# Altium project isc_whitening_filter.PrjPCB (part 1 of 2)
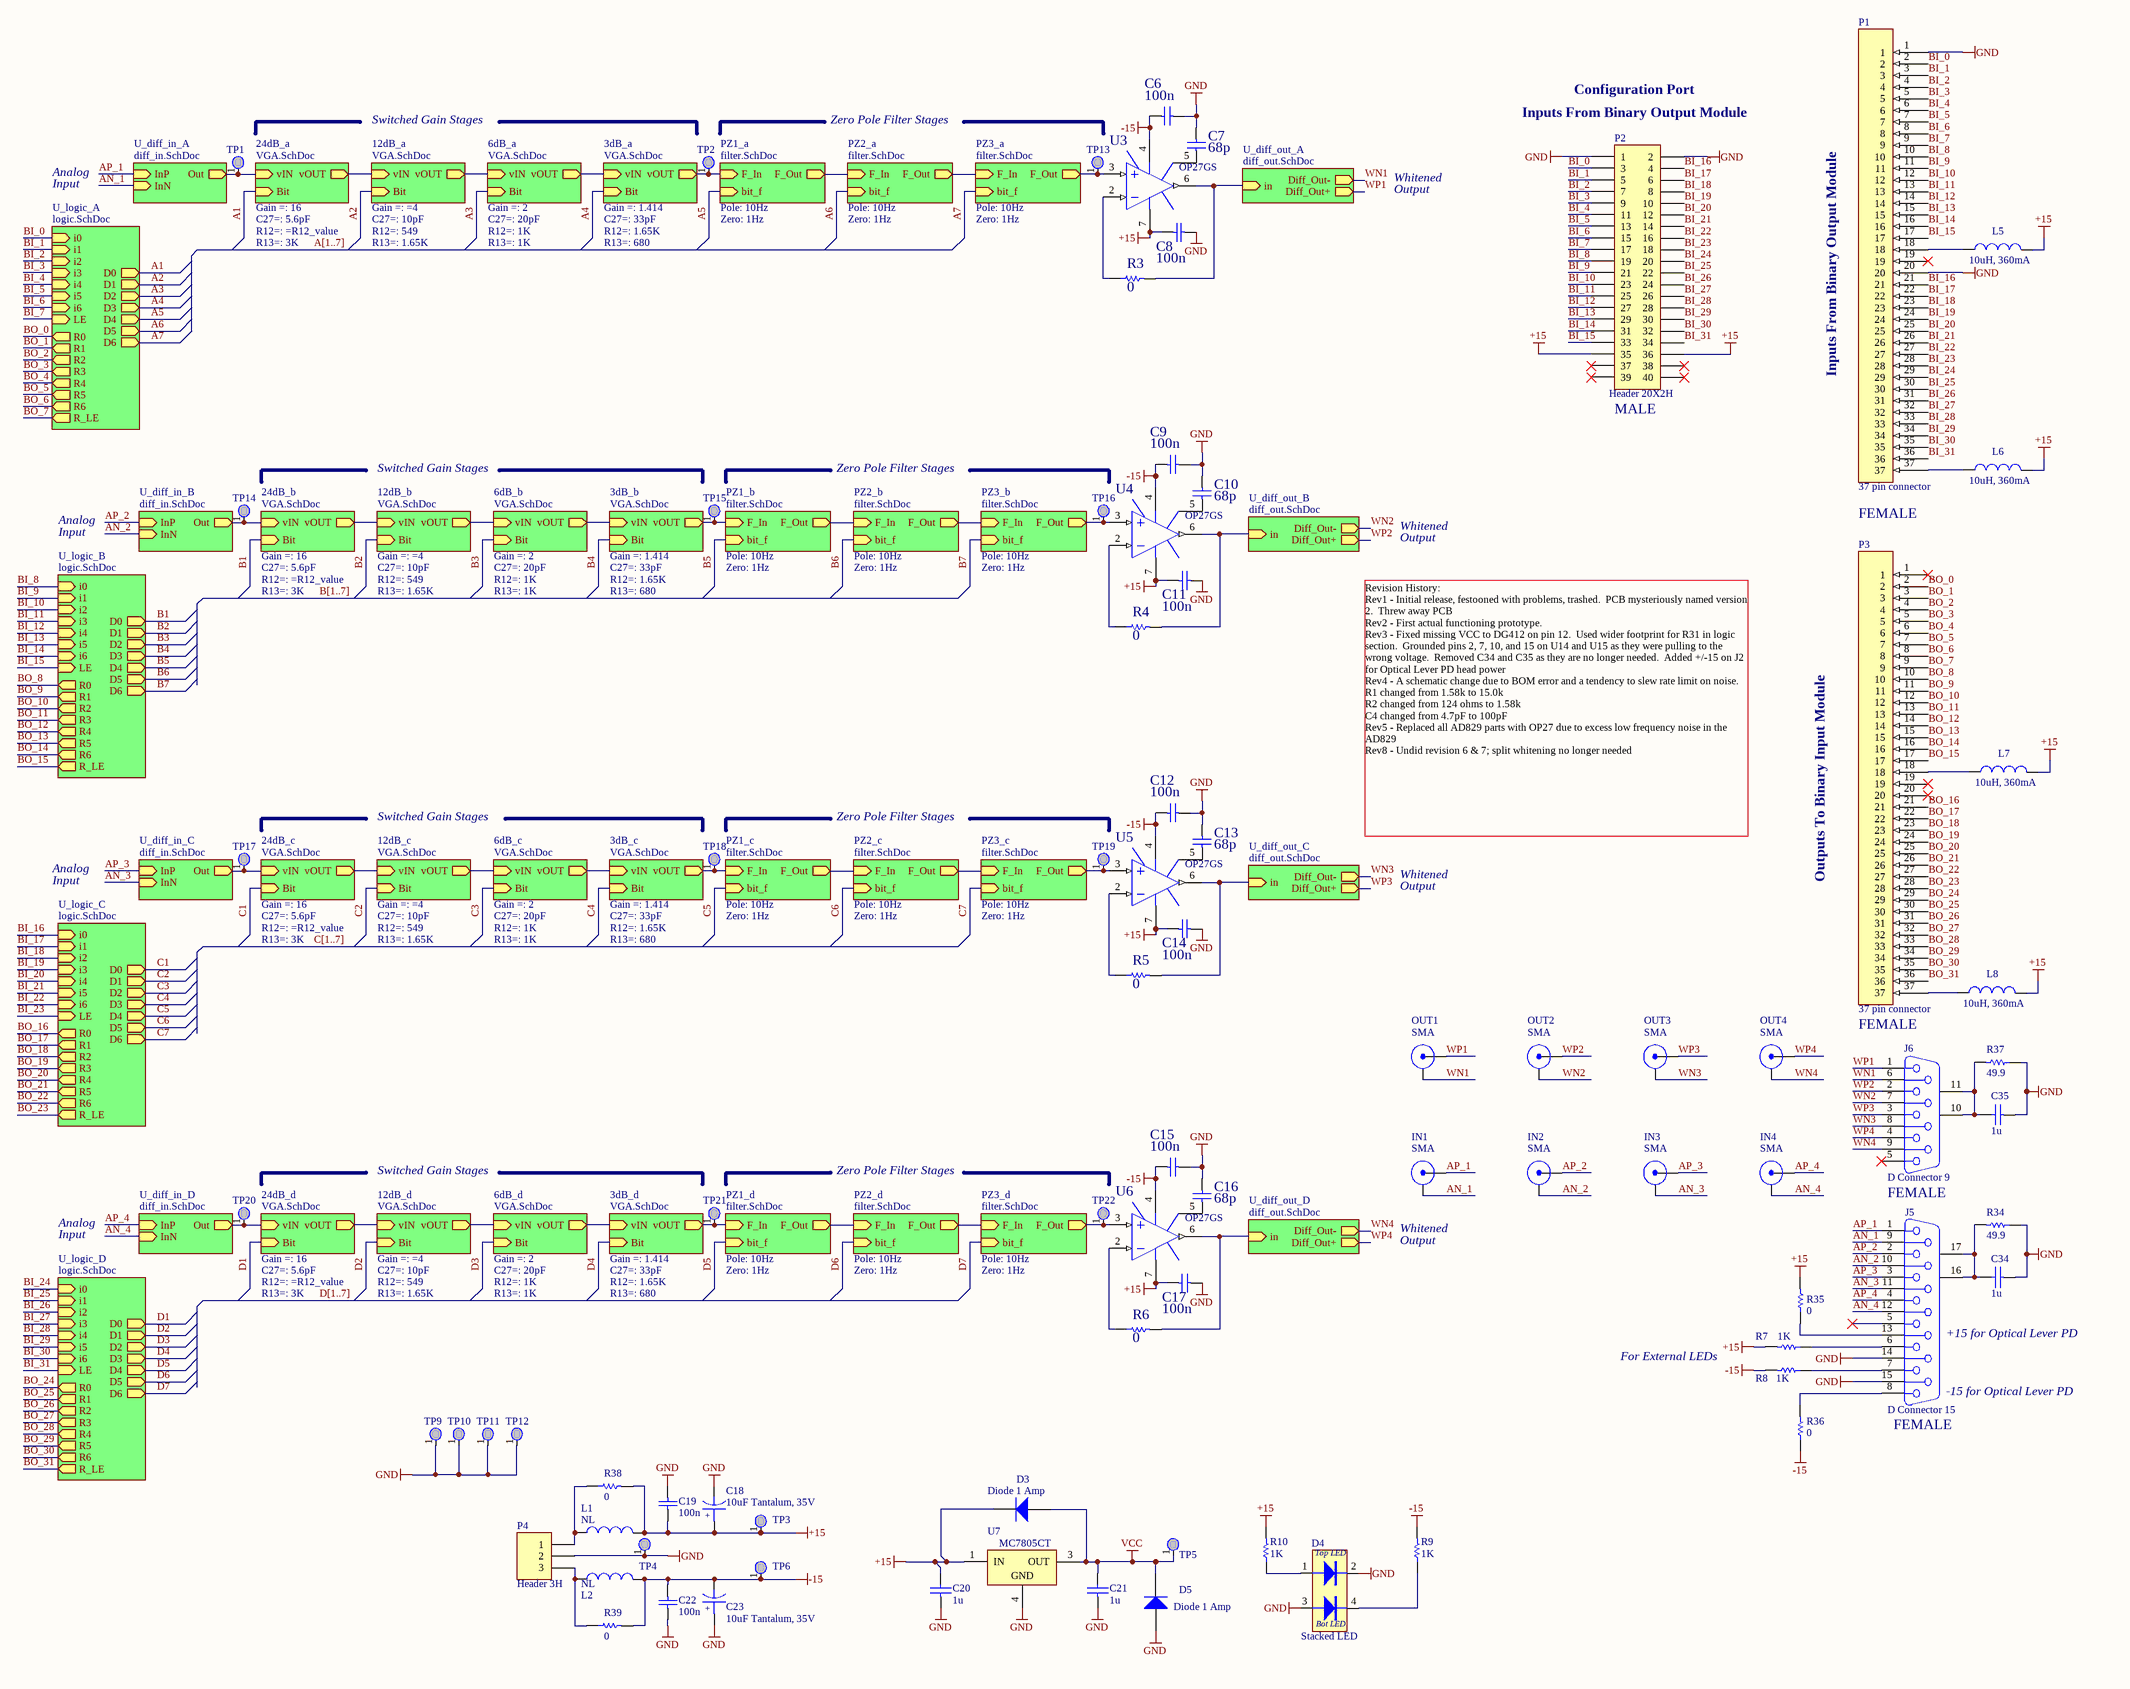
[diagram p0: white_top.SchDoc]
DCC: D1001530; REV: 8
6 sheets, 550 parts. Net scope: hierarchical (ports join the sheet entries above them; power ports are global).
Board file: isc_whitening_filter.PcbDoc
Sheets:
  white_top.SchDoc
    24dB_a = VGA.SchDoc
    12dB_a = VGA.SchDoc
    6dB_a = VGA.SchDoc
    3dB_a = VGA.SchDoc
    U_diff_in_A = diff_in.SchDoc
    U_diff_out_A = diff_out.SchDoc
    U_logic_A = logic.SchDoc
    U_diff_in_B = diff_in.SchDoc
    U_diff_out_B = diff_out.SchDoc
    U_logic_B = logic.SchDoc
    U_diff_in_C = diff_in.SchDoc
    U_diff_out_C = diff_out.SchDoc
    U_logic_C = logic.SchDoc
    U_diff_in_D = diff_in.SchDoc
    U_diff_out_D = diff_out.SchDoc
    U_logic_D = logic.SchDoc
    24dB_b = VGA.SchDoc
    12dB_b = VGA.SchDoc
    12dB_c = VGA.SchDoc
    12dB_d = VGA.SchDoc
    24dB_c = VGA.SchDoc
    24dB_d = VGA.SchDoc
    6dB_b = VGA.SchDoc
    6dB_c = VGA.SchDoc
    6dB_d = VGA.SchDoc
    3dB_b = VGA.SchDoc
    3dB_c = VGA.SchDoc
    3dB_d = VGA.SchDoc
    PZ1_b = filter.SchDoc
    PZ2_b = filter.SchDoc
    PZ3_b = filter.SchDoc
    PZ1_a = filter.SchDoc
    PZ2_a = filter.SchDoc
    PZ3_a = filter.SchDoc
    PZ1_c = filter.SchDoc
    PZ2_c = filter.SchDoc
    PZ3_c = filter.SchDoc
    PZ1_d = filter.SchDoc
    PZ2_d = filter.SchDoc
    PZ3_d = filter.SchDoc

## Sheet white_top.SchDoc: aLIGO ISC Whitening Filter
size C; SchematicNumber: DYYYYYYY-VX; PcbNumber: DXXXXXXX-VX; LastEdit: 06 Oct 2010; PageSetup: Record=PageOptions¦CenterHorizontal=True¦CenterVertical=True¦PrintScale=0.70¦XCorrection=1.00¦YCorrection=1.00¦PrintKind=0¦BorderSize=5000000¦LeftOffset=0¦BottomOffset=0¦Orientation=2¦PaperLength=4318¦PaperWidth=2794¦Scale=100¦PaperSource=7¦PrintQuality=600¦MediaType=1¦DitherType=10¦PaperKind=11x17¦PrintScaleMode=1; Organization: LIGO Laboratory; Address1: California Institute of Technology; Address2: Massachusetts Institute of Technology; DocumentNumber: D1001530; Revision: 8; SheetNumber: 1; SheetTotal: 6; Engineer: R.  Abbott

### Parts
C6  100n  [3216[1206]]
C7  68p  [3216[1206]]
C8  100n  [3216[1206]]
C9  100n  [3216[1206]]
C10  68p  [3216[1206]]
C11  100n  [3216[1206]]
C12  100n  [3216[1206]]
C13  68p  [3216[1206]]
C14  100n  [3216[1206]]
C15  100n  [3216[1206]]
C16  68p  [3216[1206]]
C17  100n  [3216[1206]]
C18  10uF Tantalum, 35V  [7343-31]
C19  100n  [3216[1206]]
C20  1u  [3216[1206]]
C21  1u  [3216[1206]]
C22  100n  [3216[1206]]
C23  10uF Tantalum, 35V  [7343-31]
C34  1u  [3216[1206]]
C35  1u  [3216[1206]]
D3  value Diode 1 Amp  [sod123]  (hidden comment: 60V, 1A Schottky)
D4  Stacked LED  [my LUMEX Dual LED]
D5  value Diode 1 Amp  [sod123]  (hidden comment: 60V, 1A Schottky)
IN1  SMA  [SMA]
IN2  SMA  [SMA]
IN3  SMA  [SMA]
IN4  SMA  [SMA]
J5  D Connector 15  [DSUB1.385-2H15]
J6  D Connector 9  [DSUB1.385-2H9]
L1  NL  [1812]
L2  NL  [1812]
L5  10uH, 360mA  [1812]
L6  10uH, 360mA  [1812]
L7  10uH, 360mA  [1812]
L8  10uH, 360mA  [1812]
OUT1  SMA  [SMA]
OUT2  SMA  [SMA]
OUT3  SMA  [SMA]
OUT4  SMA  [SMA]
P1  37 pin connector  [DB37/F/RA/125MT]
P2  Header 20X2H  [MY_40-pin_Header_RA]
P3  37 pin connector  [DB37/F/RA/125MT]
P4  Header 3H  [Molex_156_RA_3]
R3  0  [3216[1206]]
R4  0  [3216[1206]]
R5  0  [3216[1206]]
R6  0  [3216[1206]]
R7  1K  [3216[1206]]
R8  1K  [3216[1206]]
R9  1K  [3216[1206]]
R10  1K  [3216[1206]]
R34  49.9  [3216[1206]]
R35  0  [3216[1206]]
R36  0  [3216[1206]]
R37  49.9  [3216[1206]]
R38  0  [3216[1206]]
R39  0  [3216[1206]]
TP1  TEST POINT  [TP_SMT_MICRO]  (value not drawn)
TP2  TEST POINT  [TP_SMT_MICRO]  (value not drawn)
TP3  TEST POINT  [TP_SMT_MICRO]  (value not drawn)
TP4  TEST POINT  [TP_SMT_MICRO]  (value not drawn)
TP5  TEST POINT  [TP_SMT_MICRO]  (value not drawn)
TP6  TEST POINT  [TP_SMT_MICRO]  (value not drawn)
TP9  TEST POINT  [TP_SMT_MICRO]  (value not drawn)
TP10  TEST POINT  [TP_SMT_MICRO]  (value not drawn)
TP11  TEST POINT  [TP_SMT_MICRO]  (value not drawn)
TP12  TEST POINT  [TP_SMT_MICRO]  (value not drawn)
TP13  TEST POINT  [TP_SMT_MICRO]  (value not drawn)
TP14  TEST POINT  [TP_SMT_MICRO]  (value not drawn)
TP15  TEST POINT  [TP_SMT_MICRO]  (value not drawn)
TP16  TEST POINT  [TP_SMT_MICRO]  (value not drawn)
TP17  TEST POINT  [TP_SMT_MICRO]  (value not drawn)
TP18  TEST POINT  [TP_SMT_MICRO]  (value not drawn)
TP19  TEST POINT  [TP_SMT_MICRO]  (value not drawn)
TP20  TEST POINT  [TP_SMT_MICRO]  (value not drawn)
TP21  TEST POINT  [TP_SMT_MICRO]  (value not drawn)
TP22  TEST POINT  [TP_SMT_MICRO]  (value not drawn)
U3  OP27GS  [SOIC127P600-8N]
U4  OP27GS  [SOIC127P600-8N]
U5  OP27GS  [SOIC127P600-8N]
U6  OP27GS  [SOIC127P600-8N]
U7  MC7805CT  [MY_TO220]

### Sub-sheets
3dB_a = VGA.SchDoc: Bit (in), vIN (in), vOUT (out)  | R12_value: 1.65K; R13_value: 680; C27_value: 33pF; Gain =: 1.414; C27=: 33pF; R12=: 1.65K; R13=: 680
3dB_b = VGA.SchDoc: Bit (in), vIN (in), vOUT (out)  | R12_value: 1.65K; R13_value: 680; C27_value: 33pF; Gain =: 1.414; C27=: 33pF; R12=: 1.65K; R13=: 680
3dB_c = VGA.SchDoc: Bit (in), vIN (in), vOUT (out)  | R12_value: 1.65K; R13_value: 680; C27_value: 33pF; Gain =: 1.414; C27=: 33pF; R12=: 1.65K; R13=: 680
3dB_d = VGA.SchDoc: Bit (in), vIN (in), vOUT (out)  | R12_value: 1.65K; R13_value: 680; C27_value: 33pF; Gain =: 1.414; C27=: 33pF; R12=: 1.65K; R13=: 680
6dB_a = VGA.SchDoc: Bit (in), vIN (in), vOUT (out)  | C27_value: 20pF; Gain =: 2; R12_Value: 1K; R13_value: 1K; R12=: 1K; R13=: 1K; C27=: 20pF
6dB_b = VGA.SchDoc: Bit (in), vIN (in), vOUT (out)  | C27_value: 20pF; Gain =: 2; R12_Value: 1K; R13_value: 1K; R12=: 1K; R13=: 1K; C27=: 20pF
6dB_c = VGA.SchDoc: Bit (in), vIN (in), vOUT (out)  | C27_value: 20pF; Gain =: 2; R12_Value: 1K; R13_value: 1K; R12=: 1K; R13=: 1K; C27=: 20pF
6dB_d = VGA.SchDoc: Bit (in), vIN (in), vOUT (out)  | C27_value: 20pF; Gain =: 2; R12_Value: 1K; R13_value: 1K; R12=: 1K; R13=: 1K; C27=: 20pF
12dB_a = VGA.SchDoc: Bit (in), vIN (in), vOUT (out)  | C27_value: 10pF; Gain =: =4; R12=: 549; R12_value: 549; R13=: 1.65K; R13_value: 1.65K; C27=: 10pF
12dB_b = VGA.SchDoc: Bit (in), vIN (in), vOUT (out)  | C27_value: 10pF; Gain =: =4; R12=: 549; R12_value: 549; R13=: 1.65K; R13_value: 1.65K; C27=: 10pF
12dB_c = VGA.SchDoc: Bit (in), vIN (in), vOUT (out)  | C27_value: 10pF; Gain =: =4; R12=: 549; R12_value: 549; R13=: 1.65K; R13_value: 1.65K; C27=: 10pF
12dB_d = VGA.SchDoc: Bit (in), vIN (in), vOUT (out)  | C27_value: 10pF; Gain =: =4; R12=: 549; R12_value: 549; R13=: 1.65K; R13_value: 1.65K; C27=: 10pF
24dB_a = VGA.SchDoc: Bit (in), vIN (in), vOUT (out)  | C27=: 5.6pF; C27_value: 5.6pF; R12=: =R12_value; R13=: 3K; R13_value: 3K; R12_value: 200; Gain =: 16
24dB_b = VGA.SchDoc: Bit (in), vIN (in), vOUT (out)  | C27=: 5.6pF; C27_value: 5.6pF; R12=: =R12_value; R13=: 3K; R13_value: 3K; R12_value: 200; Gain =: 16
24dB_c = VGA.SchDoc: Bit (in), vIN (in), vOUT (out)  | C27=: 5.6pF; C27_value: 5.6pF; R12=: =R12_value; R13=: 3K; R13_value: 3K; R12_value: 200; Gain =: 16
24dB_d = VGA.SchDoc: Bit (in), vIN (in), vOUT (out)  | C27=: 5.6pF; C27_value: 5.6pF; R12=: =R12_value; R13=: 3K; R13_value: 3K; R12_value: 200; Gain =: 16
PZ1_a = filter.SchDoc: bit_f (in), F_Out (out), F_In (in)  | Pole: 10Hz; Zero: 1Hz; C5_value: 10e-6
PZ1_b = filter.SchDoc: bit_f (in), F_Out (out), F_In (in)  | Pole: 10Hz; Zero: 1Hz; C5_value: 10e-6
PZ1_c = filter.SchDoc: bit_f (in), F_Out (out), F_In (in)  | Pole: 10Hz; Zero: 1Hz; C5_value: 10e-6
PZ1_d = filter.SchDoc: bit_f (in), F_Out (out), F_In (in)  | Pole: 10Hz; Zero: 1Hz; C5_value: 10e-6
PZ2_a = filter.SchDoc: bit_f (in), F_Out (out), F_In (in)  | Pole: 10Hz; Zero: 1Hz; C5_value: 10e-6
PZ2_b = filter.SchDoc: bit_f (in), F_Out (out), F_In (in)  | Pole: 10Hz; Zero: 1Hz; C5_value: 10e-6
PZ2_c = filter.SchDoc: bit_f (in), F_Out (out), F_In (in)  | Pole: 10Hz; Zero: 1Hz; C5_value: 10e-6
PZ2_d = filter.SchDoc: bit_f (in), F_Out (out), F_In (in)  | Pole: 10Hz; Zero: 1Hz; C5_value: 10e-6
PZ3_a = filter.SchDoc: bit_f (in), F_Out (out), F_In (in)  | Pole: 10Hz; Zero: 1Hz; C5_value: 10e-6
PZ3_b = filter.SchDoc: bit_f (in), F_Out (out), F_In (in)  | Pole: 10Hz; Zero: 1Hz; C5_value: 10e-6
PZ3_c = filter.SchDoc: bit_f (in), F_Out (out), F_In (in)  | Pole: 10Hz; Zero: 1Hz; C5_value: 10e-6
PZ3_d = filter.SchDoc: bit_f (in), F_Out (out), F_In (in)  | Pole: 10Hz; Zero: 1Hz; C5_value: 10e-6
U_diff_in_A = diff_in.SchDoc: InP (in), InN (in), Out (out)
U_diff_in_B = diff_in.SchDoc: InP (in), InN (in), Out (out)
U_diff_in_C = diff_in.SchDoc: InP (in), InN (in), Out (out)
U_diff_in_D = diff_in.SchDoc: InP (in), InN (in), Out (out)
U_diff_out_A = diff_out.SchDoc: Diff_Out- (out), Diff_Out+ (out), in (in)
U_diff_out_B = diff_out.SchDoc: Diff_Out- (out), Diff_Out+ (out), in (in)
U_diff_out_C = diff_out.SchDoc: Diff_Out- (out), Diff_Out+ (out), in (in)
U_diff_out_D = diff_out.SchDoc: Diff_Out- (out), Diff_Out+ (out), in (in)
U_logic_A = logic.SchDoc: D0 (out), D1 (out), D2 (out), D3 (out), D4 (out), D5 (out), D6 (out), R0 (out), R1 (out), R2 (out), R3 (out), R4 (out), R5 (out), R6 (out), R_LE (out), i0 (in), i1 (in), i2 (in), i3 (in), i4 (in), i5 (in), i6 (in), LE (in)
U_logic_B = logic.SchDoc: D0 (out), D1 (out), D2 (out), D3 (out), D4 (out), D5 (out), D6 (out), R0 (out), R1 (out), R2 (out), R3 (out), R4 (out), R5 (out), R6 (out), R_LE (out), i0 (in), i1 (in), i2 (in), i3 (in), i4 (in), i5 (in), i6 (in), LE (in)
U_logic_C = logic.SchDoc: D0 (out), D1 (out), D2 (out), D3 (out), D4 (out), D5 (out), D6 (out), R0 (out), R1 (out), R2 (out), R3 (out), R4 (out), R5 (out), R6 (out), R_LE (out), i0 (in), i1 (in), i2 (in), i3 (in), i4 (in), i5 (in), i6 (in), LE (in)
U_logic_D = logic.SchDoc: D0 (out), D1 (out), D2 (out), D3 (out), D4 (out), D5 (out), D6 (out), R0 (out), R1 (out), R2 (out), R3 (out), R4 (out), R5 (out), R6 (out), R_LE (out), i0 (in), i1 (in), i2 (in), i3 (in), i4 (in), i5 (in), i6 (in), LE (in)

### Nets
+15: C8.2 C11.2 C14.2 C17.2 C18.1 C19.1 C20.2 D3.2(K) L1.2 L5.2 L6.2 L7.2 L8.2 P2.35 P2.36 R7.2 R10.2 R35.2 R38.2 TP3.1 U3.7(V+) U4.7(V+) U5.7(V+) U6.7(V+) U7.1(IN)
-15: C6.2 C9.2 C12.2 C15.2 C22.1 C23.2 L2.2 R8.2 R9.2 R36.1 R39.2 TP6.1 U3.4(V-) U4.4(V-) U5.4(V-) U6.4(V-)
GND: C6.1 C7.1 C8.1 C9.1 C10.1 C11.1 C12.1 C13.1 C14.1 C15.1 C16.1 C17.1 C18.2 C19.2 C20.1 C21.1 C22.2 C23.1 C34.1 C35.1 D4.2(CATHODE) D4.3(ANODE) D5.1(A) J5.14 J5.15 P1.1 P1.20 P2.1 P2.2 P4.2 R34.1 R37.1 TP4.1 TP9.1 TP10.1 TP11.1 TP12.1 U7.4(GND)
VCC: C21.2 D3.1(A) D5.2(K) TP5.1 U7.3(OUT)
A1: sheet 24dB_a/Bit, sheet U_logic_A/D0
A2: sheet 12dB_a/Bit, sheet U_logic_A/D1
A3: sheet 6dB_a/Bit, sheet U_logic_A/D2
A4: sheet 3dB_a/Bit, sheet U_logic_A/D3
A5: sheet U_logic_A/D4, sheet PZ1_a/bit_f
A6: sheet U_logic_A/D5, sheet PZ2_a/bit_f
A7: sheet U_logic_A/D6, sheet PZ3_a/bit_f
AN_1: IN1.2(Y) J5.9 ; sheet U_diff_in_A/InN
AN_2: IN2.2(Y) J5.10 ; sheet U_diff_in_B/InN
AN_3: IN3.2(Y) J5.11 ; sheet U_diff_in_C/InN
AN_4: IN4.2(Y) J5.12 ; sheet U_diff_in_D/InN
AP_1: IN1.1(X) J5.1 ; sheet U_diff_in_A/InP
AP_2: IN2.1(X) J5.2 ; sheet U_diff_in_B/InP
AP_3: IN3.1(X) J5.3 ; sheet U_diff_in_C/InP
AP_4: IN4.1(X) J5.4 ; sheet U_diff_in_D/InP
B1: sheet U_logic_B/D0, sheet 24dB_b/Bit
B2: sheet U_logic_B/D1, sheet 12dB_b/Bit
B3: sheet U_logic_B/D2, sheet 6dB_b/Bit
B4: sheet U_logic_B/D3, sheet 3dB_b/Bit
B5: sheet U_logic_B/D4, sheet PZ1_b/bit_f
B6: sheet U_logic_B/D5, sheet PZ2_b/bit_f
B7: sheet U_logic_B/D6, sheet PZ3_b/bit_f
BI_0: P1.2 P2.3 ; sheet U_logic_A/i0
BI_1: P1.3 P2.5 ; sheet U_logic_A/i1
BI_2: P1.4 P2.7 ; sheet U_logic_A/i2
BI_3: P1.5 P2.9 ; sheet U_logic_A/i3
BI_4: P1.6 P2.11 ; sheet U_logic_A/i4
BI_5: P1.7 P2.13 ; sheet U_logic_A/i5
BI_6: P1.8 P2.15 ; sheet U_logic_A/i6
BI_7: P1.9 P2.17 ; sheet U_logic_A/LE
BI_8: P1.10 P2.19 ; sheet U_logic_B/i0
BI_9: P1.11 P2.21 ; sheet U_logic_B/i1
BI_10: P1.12 P2.23 ; sheet U_logic_B/i2
BI_11: P1.13 P2.25 ; sheet U_logic_B/i3
BI_12: P1.14 P2.27 ; sheet U_logic_B/i4
BI_13: P1.15 P2.29 ; sheet U_logic_B/i5
BI_14: P1.16 P2.31 ; sheet U_logic_B/i6
BI_15: P1.17 P2.33 ; sheet U_logic_B/LE
BI_16: P1.21 P2.4 ; sheet U_logic_C/i0
BI_17: P1.22 P2.6 ; sheet U_logic_C/i1
BI_18: P1.23 P2.8 ; sheet U_logic_C/i2
BI_19: P1.24 P2.10 ; sheet U_logic_C/i3
BI_20: P1.25 P2.12 ; sheet U_logic_C/i4
BI_21: P1.26 P2.14 ; sheet U_logic_C/i5
BI_22: P1.27 P2.16 ; sheet U_logic_C/i6
BI_23: P1.28 P2.18 ; sheet U_logic_C/LE
BI_24: P1.29 P2.20 ; sheet U_logic_D/i0
BI_25: P1.30 P2.22 ; sheet U_logic_D/i1
BI_26: P1.31 P2.24 ; sheet U_logic_D/i2
BI_27: P1.32 P2.26 ; sheet U_logic_D/i3
BI_28: P1.33 P2.28 ; sheet U_logic_D/i4
BI_29: P1.34 P2.30 ; sheet U_logic_D/i5
BI_30: P1.35 P2.32 ; sheet U_logic_D/i6
BI_31: P1.36 P2.34 ; sheet U_logic_D/LE
BO_0: P3.2 ; sheet U_logic_A/R0
BO_1: P3.3 ; sheet U_logic_A/R1
BO_2: P3.4 ; sheet U_logic_A/R2
BO_3: P3.5 ; sheet U_logic_A/R3
BO_4: P3.6 ; sheet U_logic_A/R4
BO_5: P3.7 ; sheet U_logic_A/R5
BO_6: P3.8 ; sheet U_logic_A/R6
BO_7: P3.9 ; sheet U_logic_A/R_LE
BO_8: P3.10 ; sheet U_logic_B/R0
BO_9: P3.11 ; sheet U_logic_B/R1
BO_10: P3.12 ; sheet U_logic_B/R2
BO_11: P3.13 ; sheet U_logic_B/R3
BO_12: P3.14 ; sheet U_logic_B/R4
BO_13: P3.15 ; sheet U_logic_B/R5
BO_14: P3.16 ; sheet U_logic_B/R6
BO_15: P3.17 ; sheet U_logic_B/R_LE
BO_16: P3.21 ; sheet U_logic_C/R0
BO_17: P3.22 ; sheet U_logic_C/R1
BO_18: P3.23 ; sheet U_logic_C/R2
BO_19: P3.24 ; sheet U_logic_C/R3
BO_20: P3.25 ; sheet U_logic_C/R4
BO_21: P3.26 ; sheet U_logic_C/R5
BO_22: P3.27 ; sheet U_logic_C/R6
BO_23: P3.28 ; sheet U_logic_C/R_LE
BO_24: P3.29 ; sheet U_logic_D/R0
BO_25: P3.30 ; sheet U_logic_D/R1
BO_26: P3.31 ; sheet U_logic_D/R2
BO_27: P3.32 ; sheet U_logic_D/R3
BO_28: P3.33 ; sheet U_logic_D/R4
BO_29: P3.34 ; sheet U_logic_D/R5
BO_30: P3.35 ; sheet U_logic_D/R6
BO_31: P3.36 ; sheet U_logic_D/R_LE
C1: sheet U_logic_C/D0, sheet 24dB_c/Bit
C2: sheet U_logic_C/D1, sheet 12dB_c/Bit
C3: sheet U_logic_C/D2, sheet 6dB_c/Bit
C4: sheet U_logic_C/D3, sheet 3dB_c/Bit
C5: sheet U_logic_C/D4, sheet PZ1_c/bit_f
C6: sheet U_logic_C/D5, sheet PZ2_c/bit_f
C7: sheet U_logic_C/D6, sheet PZ3_c/bit_f
D1: sheet U_logic_D/D0, sheet 24dB_d/Bit
D2: sheet U_logic_D/D1, sheet 12dB_d/Bit
D3: sheet U_logic_D/D2, sheet 6dB_d/Bit
D4: sheet U_logic_D/D3, sheet 3dB_d/Bit
D5: sheet U_logic_D/D4, sheet PZ1_d/bit_f
D6: sheet U_logic_D/D5, sheet PZ2_d/bit_f
D7: sheet U_logic_D/D6, sheet PZ3_d/bit_f
WN1: J6.6 OUT1.2(Y) ; sheet U_diff_out_A/Diff_Out-
WN2: J6.7 OUT2.2(Y) ; sheet U_diff_out_B/Diff_Out-
WN3: J6.8 OUT3.2(Y) ; sheet U_diff_out_C/Diff_Out-
WN4: J6.9 OUT4.2(Y) ; sheet U_diff_out_D/Diff_Out-
WP1: J6.1 OUT1.1(X) ; sheet U_diff_out_A/Diff_Out+
WP2: J6.2 OUT2.1(X) ; sheet U_diff_out_B/Diff_Out+
WP3: J6.3 OUT3.1(X) ; sheet U_diff_out_C/Diff_Out+
WP4: J6.4 OUT4.1(X) ; sheet U_diff_out_D/Diff_Out+
NetC7_2: C7.2 U3.5(NUL)
NetC10_2: C10.2 U4.5(NUL)
NetC13_2: C13.2 U5.5(NUL)
NetC16_2: C16.2 U6.5(NUL)
NetC34_2: C34.2 J5.16(MH1) J5.17(MH2) R34.2
NetC35_2: C35.2 J6.10(MH1) J6.11(MH2) R37.2
NetC39_U_diff_in_A_2: TP1.1 ; sheet 24dB_a/vIN, sheet U_diff_in_A/Out
NetC39_U_diff_in_B_2: TP14.1 ; sheet U_diff_in_B/Out, sheet 24dB_b/vIN
NetC39_U_diff_in_C_2: TP17.1 ; sheet U_diff_in_C/Out, sheet 24dB_c/vIN
NetC39_U_diff_in_D_2: TP20.1 ; sheet U_diff_in_D/Out, sheet 24dB_d/vIN
NetD4_1: D4.1(COM) R10.1
NetD4_4: D4.4(ANODE) R9.1
NetJ5_6: J5.6 R7.1
NetJ5_7: J5.7 R8.1
NetJ5_8: J5.8 R36.2
NetJ5_13: J5.13 R35.1
NetL1_1: L1.1 P4.1 R38.1
NetL2_1: L2.1 P4.3 R39.1
NetL5_1: L5.1 P1.18
NetL6_1: L6.1 P1.37
NetL7_1: L7.1 P3.18
NetL8_1: L8.1 P3.37
NetR3_1: R3.1 U3.2(IN-)
NetR3_2: R3.2 U3.6(OUT) ; sheet U_diff_out_A/in
NetR4_1: R4.1 U4.2(IN-)
NetR4_2: R4.2 U4.6(OUT) ; sheet U_diff_out_B/in
NetR5_1: R5.1 U5.2(IN-)
NetR5_2: R5.2 U5.6(OUT) ; sheet U_diff_out_C/in
NetR6_1: R6.1 U6.2(IN-)
NetR6_2: R6.2 U6.6(OUT) ; sheet U_diff_out_D/in
NetTP2_1: TP2.1 ; sheet 3dB_a/vOUT, sheet PZ1_a/F_In
NetTP13_1: TP13.1 U3.3(IN+) ; sheet PZ3_a/F_Out
NetTP15_1: TP15.1 ; sheet 3dB_b/vOUT, sheet PZ1_b/F_In
NetTP16_1: TP16.1 U4.3(IN+) ; sheet PZ3_b/F_Out
NetTP18_1: TP18.1 ; sheet 3dB_c/vOUT, sheet PZ1_c/F_In
NetTP19_1: TP19.1 U5.3(IN+) ; sheet PZ3_c/F_Out
NetTP21_1: TP21.1 ; sheet 3dB_d/vOUT, sheet PZ1_d/F_In
NetTP22_1: TP22.1 U6.3(IN+) ; sheet PZ3_d/F_Out
NetU2_PZ1_a_11: sheet PZ1_a/F_Out, sheet PZ2_a/F_In
NetU2_PZ1_b_11: sheet PZ1_b/F_Out, sheet PZ2_b/F_In
NetU2_PZ1_c_11: sheet PZ1_c/F_Out, sheet PZ2_c/F_In
NetU2_PZ1_d_11: sheet PZ1_d/F_Out, sheet PZ2_d/F_In
NetU2_PZ2_a_11: sheet PZ2_a/F_Out, sheet PZ3_a/F_In
NetU2_PZ2_b_11: sheet PZ2_b/F_Out, sheet PZ3_b/F_In
NetU2_PZ2_c_11: sheet PZ2_c/F_Out, sheet PZ3_c/F_In
NetU2_PZ2_d_11: sheet PZ2_d/F_Out, sheet PZ3_d/F_In
NetU8_3dB_a_4: sheet 6dB_a/vOUT, sheet 3dB_a/vIN
NetU8_3dB_b_4: sheet 6dB_b/vOUT, sheet 3dB_b/vIN
NetU8_3dB_c_4: sheet 6dB_c/vOUT, sheet 3dB_c/vIN
NetU8_3dB_d_4: sheet 6dB_d/vOUT, sheet 3dB_d/vIN
NetU8_6dB_a_4: sheet 12dB_a/vOUT, sheet 6dB_a/vIN
NetU8_6dB_b_4: sheet 12dB_b/vOUT, sheet 6dB_b/vIN
NetU8_6dB_c_4: sheet 12dB_c/vOUT, sheet 6dB_c/vIN
NetU8_6dB_d_4: sheet 12dB_d/vOUT, sheet 6dB_d/vIN
NetU8_12dB_a_4: sheet 24dB_a/vOUT, sheet 12dB_a/vIN
NetU8_12dB_b_4: sheet 24dB_b/vOUT, sheet 12dB_b/vIN
NetU8_12dB_c_4: sheet 12dB_c/vIN, sheet 24dB_c/vOUT
NetU8_12dB_d_4: sheet 12dB_d/vIN, sheet 24dB_d/vOUT

Not connected (* = marked no-connect by the designer): J5 5*; J6 5*; P1 19*; P2 37* 38* 39* 40*; P3 1* 19* 20*; U3 1(NUL) 8(NC); U4 1(NUL) 8(NC); U5 1(NUL) 8(NC); U6 1(NUL) 8(NC)

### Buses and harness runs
bus A[1..7]
bus B[1..7]
bus C[1..7]
bus D[1..7]

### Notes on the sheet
- Configuration Port
- Switched Gain Stages
- Zero Pole Filter Stages
- (near P2) Inputs From Binary Output Module
- Analog
- Input
- Whitened
- Output
- Inputs From Binary Output Module
- (near P2) MALE
- FEMALE
- Revision History:
  Rev1 - Initial release, festooned with problems, trashed.  PCB mysteriously named version 2.  Threw away PCB
  Rev2 - First actual functioning prototype.
  Rev3 - Fixed missing VCC to DG412 on pin 12.  Used wider footprint for R31 in logic section.  Grounded pins 2, 7, 10, and 15 on U14 and U15 as they were pulling to the wrong voltage.  Removed C34 and C35 as they are no longer needed.  Added +/-15 on J2 for Optical Lever PD head power
  Rev4 - A schematic change due to BOM error and a tendency to slew rate limit on noise.
  R1 changed from 1.58k to 15.0k
  R2 changed from 124 ohms to 1.58k
  C4 changed from 4.7pF to 100pF
  Rev5 - Replaced all AD829 parts with OP27 due to excess low frequency noise in the AD829
  Rev8 - Undid revision 6 & 7; split whitening no longer needed
- Outputs To Binary Input Module
- (near IN1) Whitened
- For External LEDs
- (near J5) +15 for Optical Lever PD
- (near J5) -15 for Optical Lever PD
- (near J5) FEMALE

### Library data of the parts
C6-C17 C19 C22 = Cap: Capacitor
C18 C23 = CAPACITOR POL: Polarized Cap
C20 C21 C34 C35 = MYCAP: Capacitor
D3 D5 = Diode: Diode 1 Amp
D4 = Dual Stacked LED: Dual Green LED
IN1-IN4 OUT1-OUT4 = SMA: SMA, PCB Mount, Right Angle
J5 = D Connector 15: 15 Position, Right Angle, Receptacle Assembly; Value: 15 pin connector Receptacle
J6 = D Connector 9: 9 Position, Right Angle,Receptacle Assembly; Value: 9 pin connector Receptacle
L1 L2 L5-L8 = INDUCTOR
P1 P3 = 37 pin connector: Standard D-Subminiature Connector 37 pin; Value: 37 pin connector Receptacle
P2 = Header 20X2H: Header, 20-Pin, Dual row, Right Angle
P4 = Header 3H: Header, 3-Pin, Right Angle
R3-R10 R34-R39 = Res1: Resistor
TP1-TP6 TP9-TP22 = TESTPT: PCB Testpoint
U3-U6 = OP184ES: Video Operational Amplifier
U7 = MC7805CD2T: Three-Terminal Positive Voltage Regulator

## Sheet VGA.SchDoc: Variable Gain Stage
size A; SchematicNumber: DYYYYYYY-VX; PcbNumber: DXXXXXXX-VX; LastEdit: 06 Oct 2010; Organization: LIGO Laboratory; Address1: California Institute of Technology; Address2: Massachusetts Institute of Technology; DocumentNumber: D1001530; Revision: 8; SheetNumber: 4; SheetTotal: 9; Engineer: R.  Abbott; PageSetup: Record=PageOptions¦CenterHorizontal=True¦CenterVertical=True¦PrintScale=1.40¦XCorrection=1.00¦YCorrection=1.00¦PrintKind=0¦BorderSize=5000000¦LeftOffset=0¦BottomOffset=0¦Orientation=2¦PaperLength=4318¦PaperWidth=2794¦Scale=100¦PaperSource=15¦PrintQuality=600¦MediaType=1¦DitherType=10¦PaperKind=11x17¦PrintScaleMode=1
Used 16 times, as channels 24dB_a, 12dB_a, 6dB_a, 3dB_a, 24dB_b, 12dB_b, 12dB_c, 12dB_d, 24dB_c, 24dB_d, 6dB_b, 6dB_c, 6dB_d, 3dB_b, 3dB_c, 3dB_d. Parts and nets are listed once, with the designators drawn on the sheet.
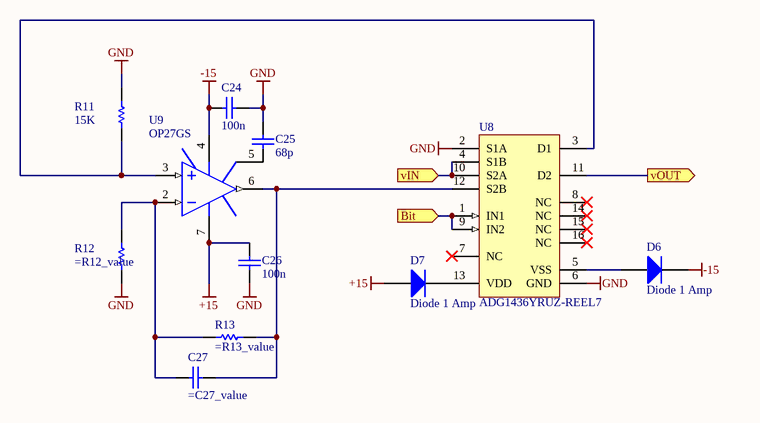
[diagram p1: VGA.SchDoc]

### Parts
C24  100n  [3216[1206]]
C25  68p  [3216[1206]]
C26  100n  [3216[1206]]
C27  (no value)  [3216[1206]]
D6  value Diode 1 Amp  [sod123]  (hidden comment: 60V, 1A Schottky)
D7  value Diode 1 Amp  [sod123]  (hidden comment: 60V, 1A Schottky)
R11  15K  [3216[1206]]
R12  (no value)  [3216[1206]]
R13  (no value)  [3216[1206]]
U8  ADG1436YRUZ-REEL7  [ADI-RU-16_L]
U9  OP27GS  [SOIC127P600-8N]

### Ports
Bit (in), vIN (in), vOUT (out)

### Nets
+15: C26.2 D7.1(A) U9.7(V+)
-15: C24.2 D6.2(K) U9.4(V-)
GND: C24.1 C25.1 C26.1 R11.2 R12.1 U8.2(S1A) U8.6(GND)
Bit: U8.1(IN1) U8.9(IN2) ; port Bit
vIN: U8.4(S1B) U8.10(S2A) ; port vIN
vOUT: U8.11(D2) ; port vOUT
NetC25_2: C25.2 U9.5(NUL)
NetC27_1: C27.1 R13.2 U8.12(S2B) U9.6(OUT)
NetC27_2: C27.2 R12.2 R13.1 U9.2(IN-)
NetD6_1: D6.1(A) U8.5(VSS)
NetD7_2: D7.2(K) U8.13(VDD)
NetR11_1: R11.1 U8.3(D1) U9.3(IN+)

Not connected (* = marked no-connect by the designer): U8 7(NC)* 8(NC)* 14(NC)* 15(NC)* 16(NC)*; U9 1(NUL) 8(NC)

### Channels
24dB_a: designators end in _24dB_a; ports Bit=A1 vIN=NetC39_U_diff_in_A_2 vOUT=NetU8_12dB_a_4
12dB_a: designators end in _12dB_a; ports Bit=A2 vIN=NetU8_12dB_a_4 vOUT=NetU8_6dB_a_4
6dB_a: designators end in _6dB_a; ports Bit=A3 vIN=NetU8_6dB_a_4 vOUT=NetU8_3dB_a_4
3dB_a: designators end in _3dB_a; ports Bit=A4 vIN=NetU8_3dB_a_4 vOUT=NetTP2_1
24dB_b: designators end in _24dB_b; ports Bit=B1 vIN=NetC39_U_diff_in_B_2 vOUT=NetU8_12dB_b_4
12dB_b: designators end in _12dB_b; ports Bit=B2 vIN=NetU8_12dB_b_4 vOUT=NetU8_6dB_b_4
12dB_c: designators end in _12dB_c; ports Bit=C2 vIN=NetU8_12dB_c_4 vOUT=NetU8_6dB_c_4
12dB_d: designators end in _12dB_d; ports Bit=D2 vIN=NetU8_12dB_d_4 vOUT=NetU8_6dB_d_4
24dB_c: designators end in _24dB_c; ports Bit=C1 vIN=NetC39_U_diff_in_C_2 vOUT=NetU8_12dB_c_4
24dB_d: designators end in _24dB_d; ports Bit=D1 vIN=NetC39_U_diff_in_D_2 vOUT=NetU8_12dB_d_4
6dB_b: designators end in _6dB_b; ports Bit=B3 vIN=NetU8_6dB_b_4 vOUT=NetU8_3dB_b_4
6dB_c: designators end in _6dB_c; ports Bit=C3 vIN=NetU8_6dB_c_4 vOUT=NetU8_3dB_c_4
6dB_d: designators end in _6dB_d; ports Bit=D3 vIN=NetU8_6dB_d_4 vOUT=NetU8_3dB_d_4
3dB_b: designators end in _3dB_b; ports Bit=B4 vIN=NetU8_3dB_b_4 vOUT=NetTP15_1
3dB_c: designators end in _3dB_c; ports Bit=C4 vIN=NetU8_3dB_c_4 vOUT=NetTP18_1
3dB_d: designators end in _3dB_d; ports Bit=D4 vIN=NetU8_3dB_d_4 vOUT=NetTP21_1

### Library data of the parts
C24-C27 = Cap: Capacitor
D6 D7 = Diode: Diode 1 Amp
R11-R13 = Res1: Resistor
U8 = CMP-0793-00126-1: +/-15 V / 12 V / +/-5 V, iCMOS, Dual SPDT Switch, 16-pin SOP (RU-16), Reel
U9 = OP184ES: Video Operational Amplifier

## Sheet diff_in.SchDoc: Differential Receiver (Whitening)
size A; Organization: LIGO Laboratory; Address1: California Institute of Technology; Address2: Massachusetts Institute of Technology; DocumentNumber: D1001530; Revision: 8; SheetNumber: 2; SheetTotal: 9; Engineer: R.  Abbott; SchematicNumber: DYYYYYYY-VX; PcbNumber: DXXXXXXX-VX; LastEdit: 06 Oct 2010; PageSetup: Record=PageOptions¦CenterHorizontal=True¦CenterVertical=True¦PrintScale=1.07¦XCorrection=1.00¦YCorrection=1.00¦PrintKind=0¦BorderSize=5000000¦LeftOffset=0¦BottomOffset=0¦Orientation=2¦PaperLength=2794¦PaperWidth=2159¦Scale=100¦PaperSource=7¦PrintQuality=600¦MediaType=1¦DitherType=10¦PaperKind=Letter¦PrintScaleMode=1
Used 4 times, as channels U_diff_in_A, U_diff_in_B, U_diff_in_C, U_diff_in_D. Parts and nets are listed once, with the designators drawn on the sheet.
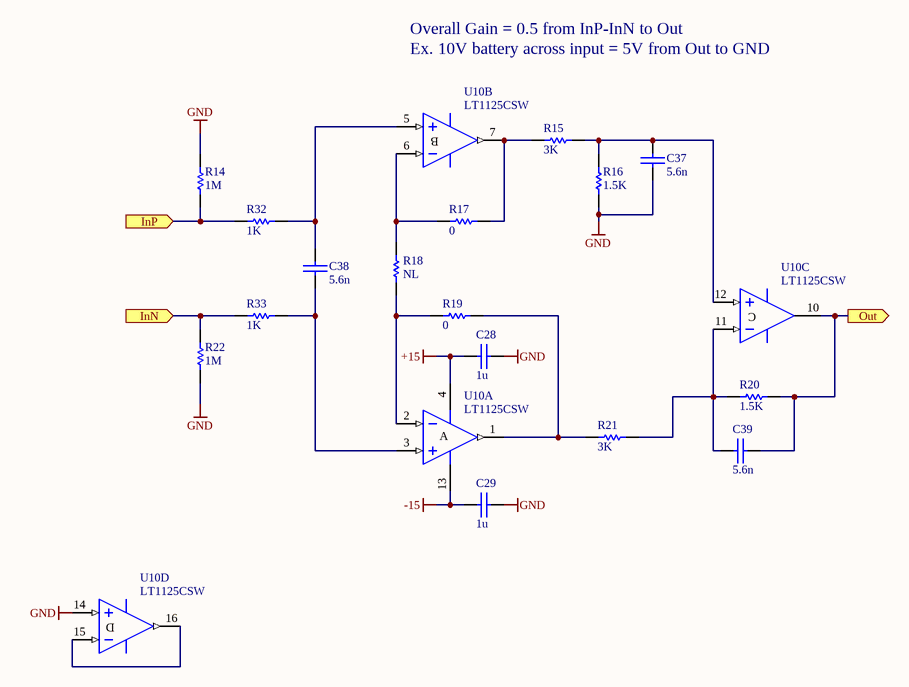
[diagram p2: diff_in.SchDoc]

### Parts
C28  1u  [3216[1206]]
C29  1u  [3216[1206]]
C37  5.6n  [3216[1206]]
C38  5.6n  [3216[1206]]
C39  5.6n  [3216[1206]]
R14  1M  [3216[1206]]
R15  3K  [3216[1206]]
R16  1.5K  [3216[1206]]
R17  0  [3216[1206]]
R18  NL  [3216[1206]]
R19  0  [3216[1206]]
R20  1.5K  [3216[1206]]
R21  3K  [3216[1206]]
R22  1M  [3216[1206]]
R32  1K  [3216[1206]]
R33  1K  [3216[1206]]
U10  LT1125CSW  [SOIC127P1030-16N]  (parts A,B,C,D of 4)

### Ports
InN (in), InP (in), Out (out)

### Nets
+15: C28.1 U10.4(V+)
-15: C29.1 U10.13(V-)
GND: C28.2 C29.2 C37.1 R14.1 R16.2 R22.2 U10.14(IN+)
InN: R22.1 R33.2 ; port InN
InP: R14.2 R32.2 ; port InP
Out: C39.2 R20.1 U10.10(OUT) ; port Out
NetC37_2: C37.2 R15.1 R16.1 U10.12(IN+)
NetC38_1: C38.1 R33.1 U10.3(IN+)
NetC38_2: C38.2 R32.1 U10.5(IN+)
NetC39_1: C39.1 R20.2 R21.1 U10.11(IN-)
NetR15_2: R15.2 R17.1 U10.7(OUT)
NetR17_2: R17.2 R18.2 U10.6(IN-)
NetR18_1: R18.1 R19.2 U10.2(IN-)
NetR19_1: R19.1 R21.2 U10.1(OUT)
NetU10_15: U10.15(IN-) U10.16(OUT)

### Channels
U_diff_in_A: designators end in _U_diff_in_A; ports InN=AN_1 InP=AP_1 Out=NetC39_U_diff_in_A_2
U_diff_in_B: designators end in _U_diff_in_B; ports InN=AN_2 InP=AP_2 Out=NetC39_U_diff_in_B_2
U_diff_in_C: designators end in _U_diff_in_C; ports InN=AN_3 InP=AP_3 Out=NetC39_U_diff_in_C_2
U_diff_in_D: designators end in _U_diff_in_D; ports InN=AN_4 InP=AP_4 Out=NetC39_U_diff_in_D_2

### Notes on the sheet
- Overall Gain = 0.5 from InP-InN to Out
- Ex. 10V battery across input = 5V from Out to GND

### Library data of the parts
C28 C29 C37-C39 = MYCAP: Capacitor
R14-R22 R32 R33 = Res1: Resistor
U10 = LT1125CS: Quad Low Noise, High-Speed Precision Operational Amplifier

## Sheet diff_out.SchDoc: Differential Driver
size A; Organization: LIGO Laboratory; Address1: California Institute of Technology; Address2: Massachusetts Institute of Technology; DocumentNumber: D1001530; Revision: 8; SheetNumber: 9; SheetTotal: 9; Engineer: R.  Abbott; SchematicNumber: DYYYYYYY-VX; PcbNumber: DXXXXXXX-VX; LastEdit: 06 Oct 2010; PageSetup: Record=PageOptions¦CenterHorizontal=True¦CenterVertical=True¦PrintScale=1.07¦XCorrection=1.00¦YCorrection=1.00¦PrintKind=0¦BorderSize=5000000¦LeftOffset=0¦BottomOffset=0¦Orientation=2¦PaperLength=2794¦PaperWidth=2159¦Scale=100¦PaperSource=7¦PrintQuality=600¦MediaType=1¦DitherType=10¦PaperKind=Letter¦PrintScaleMode=1
Used 4 times, as channels U_diff_out_A, U_diff_out_B, U_diff_out_C, U_diff_out_D. Parts and nets are listed once, with the designators drawn on the sheet.
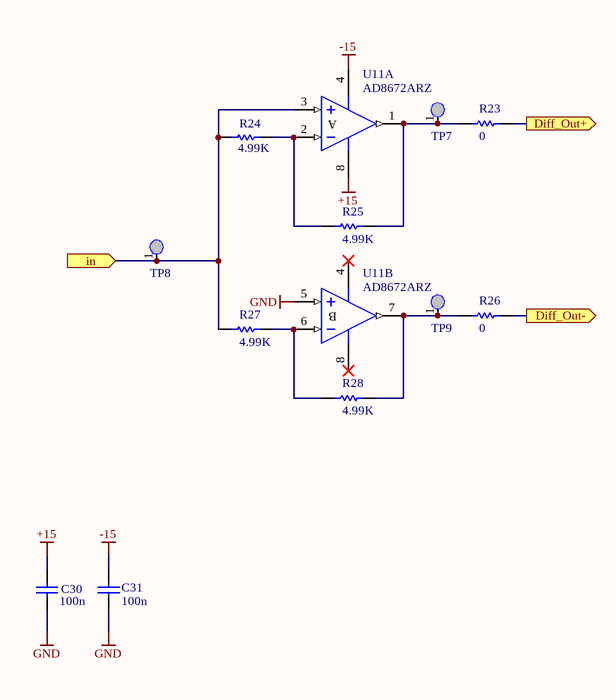
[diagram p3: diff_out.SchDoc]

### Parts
C30  100n  [3216[1206]]
C31  100n  [3216[1206]]
R23  0  [3216[1206]]
R24  4.99K  [3216[1206]]
R25  4.99K  [3216[1206]]
R26  0  [3216[1206]]
R27  4.99K  [3216[1206]]
R28  4.99K  [3216[1206]]
TP7  TEST POINT  [TP_SMT_MICRO]  (value not drawn)
TP8  TEST POINT  [TP_SMT_MICRO]  (value not drawn)
TP9  TEST POINT  [TP_SMT_MICRO]  (value not drawn)
U11  AD8672ARZ  [SOIC127P600-8N]  (parts A,B of 2)

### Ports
Diff_Out+ (out), Diff_Out- (out), in (in)

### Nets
+15: C30.1 U11.8(V+)
-15: C31.1 U11.4(V-)
GND: C30.2 C31.2 U11.5(IN+)
Diff_Out+: R23.2 ; port Diff_Out+
Diff_Out-: R26.2 ; port Diff_Out-
in: R24.1 R27.1 TP8.1 U11.3(IN+) ; port in
NetR23_1: R23.1 R25.2 TP7.1 U11.1(OUT)
NetR24_2: R24.2 R25.1 U11.2(IN-)
NetR26_1: R26.1 R28.2 TP9.1 U11.7(OUT)
NetR27_2: R27.2 R28.1 U11.6(IN-)

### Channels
U_diff_out_A: designators end in _U_diff_out_A; ports Diff_Out+=WP1 Diff_Out-=WN1 in=NetR3_2
U_diff_out_B: designators end in _U_diff_out_B; ports Diff_Out+=WP2 Diff_Out-=WN2 in=NetR4_2
U_diff_out_C: designators end in _U_diff_out_C; ports Diff_Out+=WP3 Diff_Out-=WN3 in=NetR5_2
U_diff_out_D: designators end in _U_diff_out_D; ports Diff_Out+=WP4 Diff_Out-=WN4 in=NetR6_2

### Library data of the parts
C30 C31 = Cap: Capacitor
R23-R28 = Res1: Resistor
TP7-TP9 = TESTPT: PCB Testpoint
U11 = AD826AR: High-Speed, Low-Power Dual Operational Amplifier

## Sheet logic.SchDoc: Switch Logic Circuit
size A; Organization: LIGO Laboratory; Address1: California Institute of Technology; Address2: Massachusetts Institute of Technology; DocumentNumber: D1001530; Revision: 8; SheetNumber: 8; SheetTotal: 9; Engineer: R.  Abbott; SchematicNumber: DYYYYYYY-VX; PcbNumber: DXXXXXXX-VX; LastEdit: 06 Oct 2010; PageSetup: Record=PageOptions¦CenterHorizontal=True¦CenterVertical=True¦PrintScale=1.07¦XCorrection=1.00¦YCorrection=1.00¦PrintKind=0¦BorderSize=5000000¦LeftOffset=0¦BottomOffset=0¦Orientation=2¦PaperLength=2794¦PaperWidth=2159¦Scale=100¦PaperSource=7¦PrintQuality=600¦MediaType=1¦DitherType=10¦PaperKind=Letter¦PrintScaleMode=1
Used 4 times, as channels U_logic_A, U_logic_B, U_logic_C, U_logic_D. Parts and nets are listed once, with the designators drawn on the sheet.
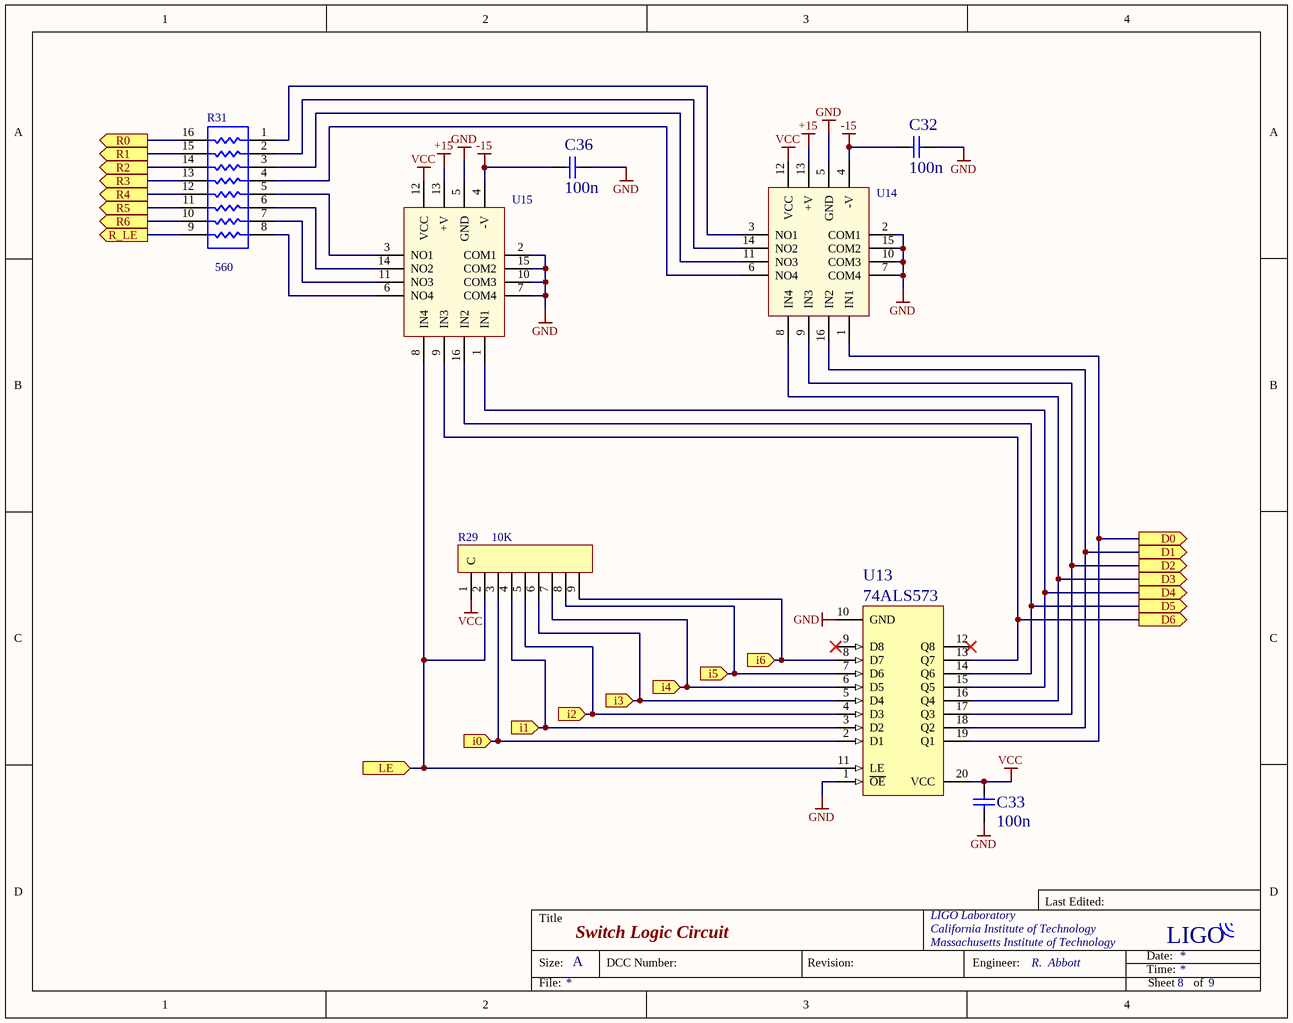
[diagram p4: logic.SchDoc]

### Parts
C32  100n  [3216[1206]]
C33  100n  [3216[1206]]
C36  100n  [3216[1206]]
R29  10K  [SRT9]
R31  560  [SOP127P760X300-16M]
U13  74ALS573  [DW020_M]
U14  DG412  [SOIC16]  (value not drawn)
U15  DG412  [SOIC16]  (value not drawn)

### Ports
D0 (out), D1 (out), D2 (out), D3 (out), D4 (out), D5 (out), D6 (out), i0 (in), i1 (in), i2 (in), i3 (in), i4 (in), i5 (in), i6 (in), LE (in), R0 (out), R1 (out), R2 (out), R3 (out), R4 (out), R5 (out), R6 (out), R_LE (out)

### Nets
+15: U14.13(+V) U15.13(+V)
-15: C32.2 C36.2 U14.4(-V) U15.4(-V)
GND: C32.1 C33.1 C36.1 U13.1(~{OE}) U13.10(GND) U14.2(COM1) U14.5(GND) U14.7(COM4) U14.10(COM3) U14.15(COM2) U15.2(COM1) U15.5(GND) U15.7(COM4) U15.10(COM3) U15.15(COM2)
VCC: C33.2 R29.1(C) U13.20(VCC) U14.12(VCC) U15.12(VCC)
D0: U13.19(Q1) U14.1(IN1) ; port D0
D1: U13.18(Q2) U14.16(IN2) ; port D1
D2: U13.17(Q3) U14.9(IN3) ; port D2
D3: U13.16(Q4) U14.8(IN4) ; port D3
D4: U13.15(Q5) U15.1(IN1) ; port D4
D5: U13.14(Q6) U15.16(IN2) ; port D5
D6: U13.13(Q7) U15.9(IN3) ; port D6
i0: R29.3 U13.2(D1) ; port i0
i1: R29.4 U13.3(D2) ; port i1
i2: R29.5 U13.4(D3) ; port i2
i3: R29.6 U13.5(D4) ; port i3
i4: R29.7 U13.6(D5) ; port i4
i5: R29.8 U13.7(D6) ; port i5
i6: R29.9 U13.8(D7) ; port i6
LE: R29.2 U13.11(LE) U15.8(IN4) ; port LE
R0: R31.16 ; port R0
R1: R31.15 ; port R1
R2: R31.14 ; port R2
R3: R31.13 ; port R3
R4: R31.12 ; port R4
R5: R31.11 ; port R5
R6: R31.10 ; port R6
R_LE: R31.9 ; port R_LE
NetR31_1: R31.1 U14.3(NO1)
NetR31_2: R31.2 U14.14(NO2)
NetR31_3: R31.3 U14.11(NO3)
NetR31_4: R31.4 U14.6(NO4)
NetR31_5: R31.5 U15.3(NO1)
NetR31_6: R31.6 U15.14(NO2)
NetR31_7: R31.7 U15.11(NO3)
NetR31_8: R31.8 U15.6(NO4)

Not connected (* = marked no-connect by the designer): U13 9(D8)* 12(Q8)*

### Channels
U_logic_A: designators end in _U_logic_A; ports D0=A1 D1=A2 D2=A3 D3=A4 D4=A5 D5=A6 D6=A7 i0=BI_0 i1=BI_1 i2=BI_2 i3=BI_3 i4=BI_4 i5=BI_5 i6=BI_6 LE=BI_7 R0=BO_0 R1=BO_1 R2=BO_2 R3=BO_3 R4=BO_4 R5=BO_5 R6=BO_6 R_LE=BO_7
U_logic_B: designators end in _U_logic_B; ports D0=B1 D1=B2 D2=B3 D3=B4 D4=B5 D5=B6 D6=B7 i0=BI_8 i1=BI_9 i2=BI_10 i3=BI_11 i4=BI_12 i5=BI_13 i6=BI_14 LE=BI_15 R0=BO_8 R1=BO_9 R2=BO_10 R3=BO_11 R4=BO_12 R5=BO_13 R6=BO_14 R_LE=BO_15
U_logic_C: designators end in _U_logic_C; ports D0=C1 D1=C2 D2=C3 D3=C4 D4=C5 D5=C6 D6=C7 i0=BI_16 i1=BI_17 i2=BI_18 i3=BI_19 i4=BI_20 i5=BI_21 i6=BI_22 LE=BI_23 R0=BO_16 R1=BO_17 R2=BO_18 R3=BO_19 R4=BO_20 R5=BO_21 R6=BO_22 R_LE=BO_23
U_logic_D: designators end in _U_logic_D; ports D0=D1 D1=D2 D2=D3 D3=D4 D4=D5 D5=D6 D6=D7 i0=BI_24 i1=BI_25 i2=BI_26 i3=BI_27 i4=BI_28 i5=BI_29 i6=BI_30 LE=BI_31 R0=BO_24 R1=BO_25 R2=BO_26 R3=BO_27 R4=BO_28 R5=BO_29 R6=BO_30 R_LE=BO_31

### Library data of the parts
C32 C33 C36 = Cap: Capacitor
R29 = RES_BUS_8: 8 Bus Resistor
R31 = Res Pack3: Isolated Resistor Network
U13 = SN74ALS573CDW: Octal D-Type Transparent Latches with 3-State Outputs
U14 U15 = DG412: Quad Analog SPST NO Switch

## Sheet filter.SchDoc: Zero-pole Stage
size A; SchematicNumber: DYYYYYYY-VX; PcbNumber: DXXXXXXX-VX; LastEdit: 06 Oct 2010; Organization: LIGO Laboratory; Address1: California Institute of Technology; Address2: Massachusetts Institute of Technology; DocumentNumber: D1001530; Revision: 8; SheetNumber: 6; SheetTotal: 9; Engineer: R.  Abbott; PageSetup: Record=PageOptions¦CenterHorizontal=True¦CenterVertical=True¦PrintScale=1.40¦XCorrection=1.00¦YCorrection=1.00¦PrintKind=0¦BorderSize=5000000¦LeftOffset=0¦BottomOffset=0¦Orientation=2¦PaperLength=4318¦PaperWidth=2794¦Scale=100¦PaperSource=7¦PrintQuality=600¦MediaType=1¦DitherType=10¦PaperKind=11x17¦PrintScaleMode=1
Used 12 times, as channels PZ1_b, PZ2_b, PZ3_b, PZ1_a, PZ2_a, PZ3_a, PZ1_c, PZ2_c, PZ3_c, PZ1_d, PZ2_d, PZ3_d. Parts and nets are listed once, with the designators drawn on the sheet.
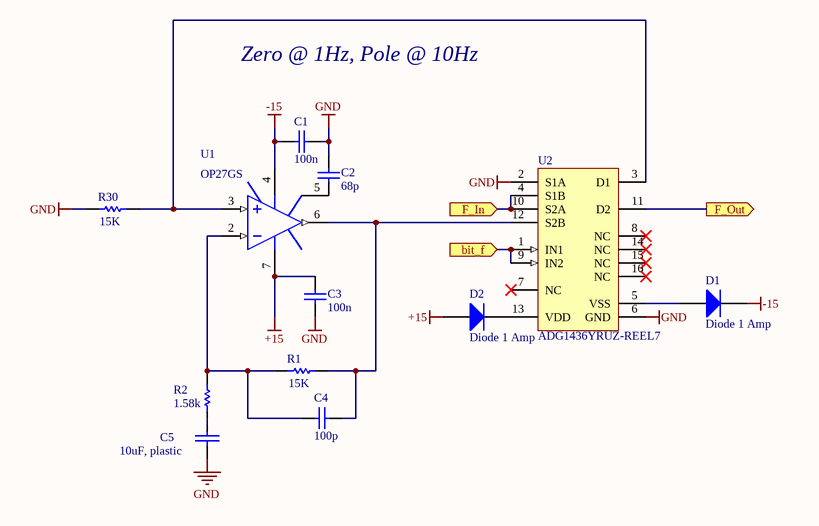
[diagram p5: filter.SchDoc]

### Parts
C1  100n  [3216[1206]]
C2  68p  [3216[1206]]
C3  100n  [3216[1206]]
C4  100p  [3216[1206]]
C5  10uF, plastic  [ECQ-E1106KF_Side]
D1  value Diode 1 Amp  [sod123]  (hidden comment: 60V, 1A Schottky)
D2  value Diode 1 Amp  [sod123]  (hidden comment: 60V, 1A Schottky)
R1  15K  [3216[1206]]
R2  1.58k  [3216[1206]]
R30  15K  [3216[1206]]
U1  OP27GS  [SOIC127P600-8N]
U2  ADG1436YRUZ-REEL7  [ADI-RU-16_L]

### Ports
bit_f (in), F_In (in), F_Out (out)

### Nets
+15: C3.2 D2.1(A) U1.7(V+)
-15: C1.2 D1.2(K) U1.4(V-)
GND: C1.1 C2.1 C3.1 C5.2 R30.2 U2.2(S1A) U2.6(GND)
bit_f: U2.1(IN1) U2.9(IN2) ; port bit_f
F_In: U2.4(S1B) U2.10(S2A) ; port F_In
F_Out: U2.11(D2) ; port F_Out
NetC2_2: C2.2 U1.5(NUL)
NetC4_1: C4.1 R1.2 R2.2 U1.2(IN-)
NetC4_2: C4.2 R1.1 U1.6(OUT) U2.12(S2B)
NetC5_1: C5.1 R2.1
NetD1_1: D1.1(A) U2.5(VSS)
NetD2_2: D2.2(K) U2.13(VDD)
NetR30_1: R30.1 U1.3(IN+) U2.3(D1)

Not connected (* = marked no-connect by the designer): U1 1(NUL) 8(NC); U2 7(NC)* 8(NC)* 14(NC)* 15(NC)* 16(NC)*

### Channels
PZ1_b: designators end in _PZ1_b; ports bit_f=B5 F_In=NetTP15_1 F_Out=NetU2_PZ1_b_11
PZ2_b: designators end in _PZ2_b; ports bit_f=B6 F_In=NetU2_PZ1_b_11 F_Out=NetU2_PZ2_b_11
PZ3_b: designators end in _PZ3_b; ports bit_f=B7 F_In=NetU2_PZ2_b_11 F_Out=NetTP16_1
PZ1_a: designators end in _PZ1_a; ports bit_f=A5 F_In=NetTP2_1 F_Out=NetU2_PZ1_a_11
PZ2_a: designators end in _PZ2_a; ports bit_f=A6 F_In=NetU2_PZ1_a_11 F_Out=NetU2_PZ2_a_11
PZ3_a: designators end in _PZ3_a; ports bit_f=A7 F_In=NetU2_PZ2_a_11 F_Out=NetTP13_1
PZ1_c: designators end in _PZ1_c; ports bit_f=C5 F_In=NetTP18_1 F_Out=NetU2_PZ1_c_11
PZ2_c: designators end in _PZ2_c; ports bit_f=C6 F_In=NetU2_PZ1_c_11 F_Out=NetU2_PZ2_c_11
PZ3_c: designators end in _PZ3_c; ports bit_f=C7 F_In=NetU2_PZ2_c_11 F_Out=NetTP19_1
PZ1_d: designators end in _PZ1_d; ports bit_f=D5 F_In=NetTP21_1 F_Out=NetU2_PZ1_d_11
PZ2_d: designators end in _PZ2_d; ports bit_f=D6 F_In=NetU2_PZ1_d_11 F_Out=NetU2_PZ2_d_11
PZ3_d: designators end in _PZ3_d; ports bit_f=D7 F_In=NetU2_PZ2_d_11 F_Out=NetTP22_1

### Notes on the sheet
- Zero @ 1Hz, Pole @ 10Hz

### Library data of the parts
C1-C4 = Cap: Capacitor
C5 = MYCAP: Capacitor
D1 D2 = Diode: Diode 1 Amp
R1 R2 R30 = Res1: Resistor
U1 = OP184ES: Video Operational Amplifier
U2 = CMP-0793-00126-1: as U8 on sheet VGA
